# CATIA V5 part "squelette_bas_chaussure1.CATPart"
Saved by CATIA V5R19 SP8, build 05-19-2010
Part number: squelette_bas_chaussure1
Bounding box of the stored display mesh (mm): x 100 to 147, y 100 to 200, z 60 to 220
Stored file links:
  G:\EU_thinkMotion\CFAO_2010\MMS_groupe2\MMS_groupe2\A reprendre\jcauchy\squelette_bas_chaussure1.CATPart
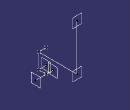
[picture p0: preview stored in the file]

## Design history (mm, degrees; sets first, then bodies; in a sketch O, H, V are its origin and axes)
Parameters
  Longueurcontact1_baschaussure1 = 100 mm
  Longueurcontact2_baschaussure1 = 120 mm
  Longueurfixation_baschaussure1 = 20 mm
  Largeur_baschaussure1 = 40 mm
  Longueurcollier4_baschaussure1 = 20 mm
Set1
  Point1: (100, 100, 100)
  Point2: (120 {= 100mm+Longueurfixation_baschaussure1}, 100, 100)
  Line1: type PtPt, FirstPoint Point1, SecondPoint Point2
  Point3: type OnCurve, Support Line1, Length 20 {= Longueurfixation_baschaussure1}
  Line2: type Angle, RefPoint Point3, Curve Line1, Support xy-plane, Start 0, End 100 {= Longueurcontact1_baschaussure1}, Angle 90
  Plane1: type Normal, Curve Line2, RefPoint vertex of Line2
  Line3: type Angle, RefPoint vertex of Line2, Curve Line2, Support yz-plane, Start 0, End 120 {= Longueurcontact2_baschaussure1}, Angle 90
  Plane2: type Tangent, Support Plane1, RefPoint vertex of Line3
  Point4: (0, 0, -40 {= -Largeur_baschaussure1}), relative to Point3
  Line4: type PtPt, FirstPoint Point3, SecondPoint Point4
  Line5: type PtDir, RefPoint Point4, Direction Line1, Start 0, End 20 {= Longueurfixation_baschaussure1}
  Plane3: type Normal, Curve Line5, RefPoint vertex of Line5
  Point5: (0, 20 {= Longueurcollier4_baschaussure1}, 0), relative to Point4
  Line6: type PtPt, FirstPoint Point4, SecondPoint Point5
  Line7: type PtDir, RefPoint Point5, Direction Line5, Start 0, End 17
  Plane4: type Normal, Curve Line7, RefPoint vertex of Line7
  Line8: type PtDir, RefPoint Point5, Direction Line7, Start 0, End 27
  Plane5: type Normal, Curve Line8, RefPoint vertex of Line8
Body1 (main body)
